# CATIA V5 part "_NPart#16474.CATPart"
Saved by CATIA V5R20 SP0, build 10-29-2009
Part number: 1BOLAØ2,3
Revision: ANY
Definition: UNKNOWN
Nomenclature: 1BOLAØ2,3
Source: Unknown
Bounding box of the stored display mesh (mm): x -1.19 to 1.19, y -1.19 to 1.19, z -1.19 to 1.19
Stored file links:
  C:\Users\Utente\Desktop\IO LAVORO\3D X SITO CF\CUMSA\3D files AE\_NPart#16474.CATPart
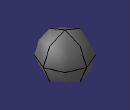
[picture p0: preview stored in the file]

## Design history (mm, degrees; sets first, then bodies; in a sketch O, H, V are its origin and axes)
Body1 "Revolución1" (main body)
  Solid1: solid without history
